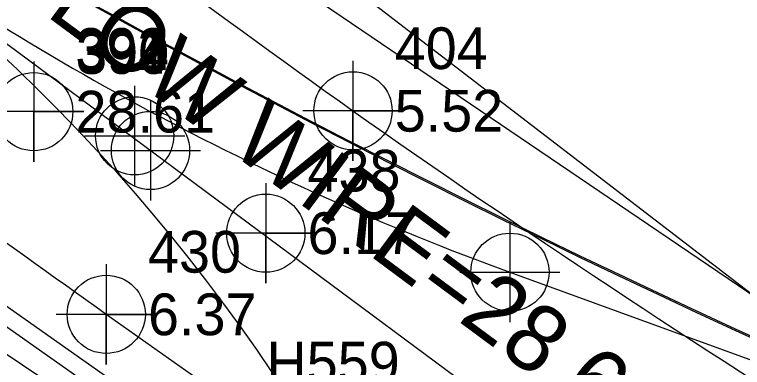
# Model space of a CAD drawing. Extents: x 2597630 to 2605918, y 617194 to 635093.
# Drawn here: x 2605052.23 to 2605095.86, y 618532.66 to 618553.82 of the extents above; entities that cross this region are included whole.
import ezdxf

# ---------------------------------------------------------------- set-up
doc = ezdxf.new("R2010")
doc.units = 0
for name, color, linetype in [('COGO Default Chain', 7, 'Continuous'), ('COGO Default Curve', 7, 'Continuous'), ('Cogo Default Point CELL', 7, 'Continuous'), ('Default Symbol CELL', 7, 'Continuous'), ('Default Symbol Cogo Elevation', 7, 'Continuous'), ('Default Symbol Cogo Number', 7, 'Continuous'), ('Default Symbol Text', 7, 'Continuous'), ('Exist DTM Crownline Cogo Elevation', 7, 'Continuous'), ('Exist DTM Crownline Cogo Number', 7, 'Continuous'), ('Exist DTM Crownline Cogo Point CELL', 7, 'Continuous'), ('Exist Horizontal Alignment', 7, 'Continuous'), ('Exist Right of Way Line', 7, 'Continuous'), ('Exist Roads EOP', 7, 'Continuous'), ('Exist Roads EOP Cogo Elevation', 7, 'Continuous'), ('Exist Roads EOP Cogo Number', 7, 'Continuous'), ('Exist Roads EOP Cogo Point CELL', 7, 'Continuous'), ('Exist Roads Soil Cogo Number', 7, 'Continuous'), ('Exist Utilities Telephone UG Cable SUE LOS C', 7, 'Continuous'), ('Exist Utilities Water UG Line SUE LOS B', 7, 'Continuous'), ('Raster_Level_3', 7, 'Continuous')]:
    doc.layers.add(name, color=color, linetype=linetype)

# ---------------------------------------------------------------- blocks, each defined once
blk = doc.blocks.new('EXIST DTM CROWNLINE COGO POINT')
at = {"layer": 'Exist DTM Crownline Cogo Point CELL'}
blk.add_lwpolyline([(0, 0.06), (0, -0.06), (0, 0), (0.06, 0), (-0.06, 0)], dxfattribs=at)
blk.add_circle((0, 0), 0.04688, dxfattribs=at)
blk = doc.blocks.new('EXIST ROADS EOP COGO POINT')
at = {"layer": 'Exist Roads EOP Cogo Point CELL'}
blk.add_lwpolyline([(0, 0.06), (0, -0.06), (0, 0), (0.06, 0), (-0.06, 0)], dxfattribs=at)
blk.add_circle((0, 0), 0.04688, dxfattribs=at)
blk = doc.blocks.new('DEFAULT SYMBOL')
at = {"layer": 'Default Symbol CELL'}
blk.add_lwpolyline([(0, 0.06), (0, -0.06), (0, 0), (0.06, 0), (-0.06, 0)], dxfattribs=at)
blk.add_circle((0, 0), 0.04688, dxfattribs=at)

msp = doc.modelspace()

# ---------------------------------------------------------------- linework, layer by layer
at = {"layer": 'COGO Default Chain'}
for p, q in [((2604635.42, 618891.582), (2605209.537, 618450.053)), ((2604635.42, 618891.582), (2605209.537, 618450.053)), ((2604906.9, 618659.448), (2605092.435, 618521.9)), ((2604906.9, 618659.448), (2605092.435, 618521.9)), ((2604906.9, 618659.448), (2605092.435, 618521.9)), ((2605081.924, 618538.367), (2605135.708, 618518.808)), ((2605081.924, 618538.367), (2605135.708, 618518.808)), ((2605081.924, 618538.367), (2605135.708, 618518.808))]:
    msp.add_line(p, q, dxfattribs=at)
for centre, radius, start, end in [((2605334.316, 619054.493), 571.893, 233.44825, 249.95735), ((2605334.316, 619054.493), 571.893, 233.44825, 249.95735), ((2605334.316, 619054.493), 571.893, 233.44825, 249.95735), ((2605138.207, 618693.141), 164.69, 233.47492, 250.01646), ((2605138.207, 618693.141), 164.69, 233.47492, 250.01646), ((2605138.207, 618693.141), 164.69, 233.47492, 250.01646), ((2604976.371, 618471.014), 110, 356.74026, 53.44825)]:
    msp.add_arc(centre, radius, start, end, dxfattribs=at)
at = {"layer": 'COGO Default Curve'}
for centre, radius, start, end in [((2605334.316, 619054.493), 571.893, 233.44825, 249.95735), ((2605334.316, 619054.493), 571.893, 233.44825, 249.95735), ((2605138.207, 618693.141), 164.69, 233.47492, 250.01646), ((2605138.207, 618693.141), 164.69, 233.47492, 250.01646), ((2604976.371, 618471.014), 110, 356.74026, 53.44825)]:
    msp.add_arc(centre, radius, start, end, dxfattribs=at)
at = {"layer": 'Cogo Default Point CELL'}
for points in [[(2605059.426, 618549.548), (2605059.426, 618546.548)], [(2605060.374, 618548.669), (2605060.374, 618545.669)], [(2605060.374, 618548.669), (2605060.374, 618545.669)], [(2605056.426, 618546.548), (2605059.426, 618546.548)], [(2605059.426, 618546.548), (2605062.426, 618546.548)], [(2605059.426, 618546.548), (2605059.426, 618543.548)], [(2605057.374, 618545.669), (2605060.374, 618545.669)], [(2605057.374, 618545.669), (2605060.374, 618545.669)], [(2605060.374, 618545.669), (2605063.374, 618545.669)], [(2605060.374, 618545.669), (2605060.374, 618542.669)], [(2605060.374, 618545.669), (2605063.374, 618545.669)], [(2605060.374, 618545.669), (2605060.374, 618542.669)], [(2605081.924, 618541.367), (2605081.924, 618538.367)], [(2605078.924, 618538.367), (2605081.924, 618538.367)], [(2605081.924, 618538.367), (2605084.924, 618538.367)], [(2605081.924, 618538.367), (2605081.924, 618535.367)]]:
    msp.add_lwpolyline(points, dxfattribs=at)
for centre in [(2605059.426, 618546.548), (2605060.374, 618545.669), (2605060.374, 618545.669), (2605081.924, 618538.367)]:
    msp.add_circle(centre, 2.344, dxfattribs=at)
at = {"layer": 'Exist Horizontal Alignment'}
msp.add_line((2604906.9, 618659.448), (2605092.435, 618521.9), dxfattribs=at)
msp.add_arc((2605334.316, 619054.493), 571.893, 233.44825, 249.95735, dxfattribs=at)
at = {"layer": 'Exist Right of Way Line'}
msp.add_arc((2605334.316, 619054.493), 541.808, 233.44825, 249.91603, dxfattribs=at)
at = {"layer": 'Exist Roads EOP'}
for points in [[(2604973.794, 618621.175), (2605003.899, 618598.528), (2605046.196, 618567.408), (2605072.515, 618548.047), (2605103.618, 618527.364), (2605140.117, 618505.161), (2605178.033, 618485.562), (2605220.739, 618472.458), (2605259.093, 618465.195), (2605301.774, 618462.969), (2605350.348, 618466.747), (2605390.569, 618472.395), (2605430.003, 618479.657), (2605472.601, 618488.42), (2605517.963, 618498.678), (2605555.274, 618508.222)], [(2605554.931, 618488.691), (2605518.323, 618479.552), (2605476.771, 618470.314), (2605429.068, 618460.66), (2605388.393, 618453.139), (2605342.247, 618446.788), (2605297.978, 618443.933), (2605250.493, 618446.948), (2605224.746, 618451.291), (2605188.067, 618461.914), (2605143.175, 618481.98), (2605101.821, 618506.05), (2605057.725, 618535.842), (2605018.828, 618564.087), (2604984.62, 618589.304), (2604956.97, 618610.183)]]:
    msp.add_spline(points, degree=3, dxfattribs=at)
at = {"layer": 'Exist Utilities Telephone UG Cable SUE LOS C'}
for points in [[(2604704.632, 618797.902), (2604709.253, 618799.967), (2604746.093, 618830.902), (2604769.465, 618803.801), (2604789.101, 618780.394), (2604811.521, 618758.153), (2604839.523, 618732.525), (2604857.937, 618716.819), (2604890.546, 618690.254), (2604917.08, 618668.966), (2604949.989, 618644.104), (2604978.651, 618623.009), (2605029.128, 618585.555), (2605062.936, 618559.757), (2605107.482, 618529.542), (2605127.562, 618516.387), (2605160.551, 618498.208), (2605196.169, 618483.139), (2605231.309, 618473.571), (2605271.708, 618467.352), (2605299.025, 618467.352), (2605327.232, 618467.352), (2605372.412, 618473.385), (2605472.154, 618492.39)], [(2605035.066, 618529.174), (2605044.701, 618541.284), (2605064.459, 618527.372), (2605084.583, 618513.704), (2605100.475, 618503.765), (2605114.433, 618495.379), (2605124.434, 618489.604), (2605135.591, 618483.21), (2605148.008, 618476.685), (2605160.516, 618470.334), (2605171.841, 618465.29), (2605179.513, 618461.899), (2605191.486, 618457.352), (2605197.211, 618455.484), (2605216.999, 618449.631), (2605228.628, 618446.625), (2605244.658, 618443.836), (2605269.573, 618441.133), (2605291.807, 618441.133), (2605291.093, 618423.377)], [(2605035.567, 618529.349), (2605044.896, 618539.924), (2605063.89, 618526.549), (2605084.036, 618512.866), (2605099.952, 618502.912), (2605113.925, 618494.517), (2605123.935, 618488.737), (2605135.109, 618482.333), (2605147.549, 618475.796), (2605160.086, 618469.431), (2605171.435, 618464.376), (2605179.133, 618460.973), (2605191.153, 618456.408), (2605196.914, 618454.529), (2605216.732, 618448.667), (2605228.417, 618445.647), (2605244.518, 618442.845), (2605269.519, 618440.133), (2605290.766, 618440.133), (2605290.933, 618424.271)]]:
    msp.add_lwpolyline(points, dxfattribs=at)
at = {"layer": 'Exist Utilities Water UG Line SUE LOS B'}
msp.add_lwpolyline([(2604726.889, 618802.825), (2604728.623, 618800.62), (2604750.622, 618775.419), (2604790.386, 618735.469), (2604815.583, 618710.966), (2604846.421, 618684.691), (2604883.421, 618655.421), (2604920.609, 618626.25), (2604956.469, 618598.67), (2605000.193, 618568.419), (2605036.439, 618543.714), (2605076.168, 618517.089), (2605118.843, 618487.791), (2605146.777, 618472.232), (2605179.699, 618456.688), (2605215.856, 618442.587), (2605263.864, 618435.28), (2605306.639, 618434.129), (2605336.924, 618437.158), (2605382.69, 618444.237), (2605417.11, 618449.886), (2605451.772, 618457.953), (2605484.983, 618464.773), (2605522.806, 618473.788)], dxfattribs=at)
at = {"layer": 'Raster_Level_3'}
msp.add_arc((2605333.954, 619054.76), 571.893, 233.49328, 249.99328, dxfattribs=at)

# ---------------------------------------------------------------- block references
at = {"layer": 'Default Symbol CELL', "xscale": 50, "yscale": 50}
msp.add_blockref('DEFAULT SYMBOL', (2605053.378, 618547.994), dxfattribs=at)
at = {"layer": 'Exist DTM Crownline Cogo Point CELL', "xscale": 50, "yscale": 50}
msp.add_blockref('EXIST DTM CROWNLINE COGO POINT', (2605067.287, 618540.706), dxfattribs=at)
msp.add_blockref('EXIST DTM CROWNLINE COGO POINT', (2605067.287, 618540.706), dxfattribs=at)
at = {"layer": 'Exist Roads EOP Cogo Point CELL', "xscale": 50, "yscale": 50}
for p in [(2605072.515, 618548.047), (2605072.515, 618548.047), (2605057.725, 618535.842), (2605057.725, 618535.842)]:
    msp.add_blockref('EXIST ROADS EOP COGO POINT', p, dxfattribs=at)

# ---------------------------------------------------------------- texts
at = {"layer": 'Default Symbol Cogo Elevation'}
for p in [(2605055.874, 618546.747), (2605055.878, 618546.744)]:
    msp.add_text('28.61', height=2.5, dxfattribs=at).set_placement(p)
at = {"layer": 'Default Symbol Cogo Number'}
for s, p in [('392', (2605055.867, 618550.501)), ('393', (2605055.874, 618550.497)), ('391', (2605055.878, 618550.494)), ('394', (2605055.904, 618550.265)), ('390', (2605055.919, 618550.258))]:
    msp.add_text(s, height=2.5, dxfattribs=at).set_placement(p)
at = {"layer": 'Default Symbol Text'}
msp.add_text("LOW WIRE=28.61'", height=4, rotation=323.4482, dxfattribs=at).set_placement((2605054.036, 618553.802))
at = {"layer": 'Exist DTM Crownline Cogo Elevation'}
msp.add_text('6.17', height=2.5, dxfattribs=at).set_placement((2605069.787, 618539.456))
at = {"layer": 'Exist DTM Crownline Cogo Number'}
msp.add_text('438', height=2.5, dxfattribs=at).set_placement((2605069.787, 618543.206))
msp.add_text('438', height=2.5, dxfattribs=at).set_placement((2605069.787, 618543.206))
at = {"layer": 'Exist Roads EOP Cogo Elevation'}
for s, p in [('5.52', (2605075.015, 618546.797)), ('6.37', (2605060.225, 618534.592))]:
    msp.add_text(s, height=2.5, dxfattribs=at).set_placement(p)
at = {"layer": 'Exist Roads EOP Cogo Number'}
for s, p in [('404', (2605075.015, 618550.547)), ('430', (2605060.225, 618538.342))]:
    msp.add_text(s, height=2.5, dxfattribs=at).set_placement(p)
at = {"layer": 'Exist Roads Soil Cogo Number'}
msp.add_text('H559', height=2.5, dxfattribs=at).set_placement((2605067.324, 618531.696))
msp.add_text('H559', height=2.5, dxfattribs=at).set_placement((2605067.324, 618531.696))

doc.saveas('drawing.dxf')
